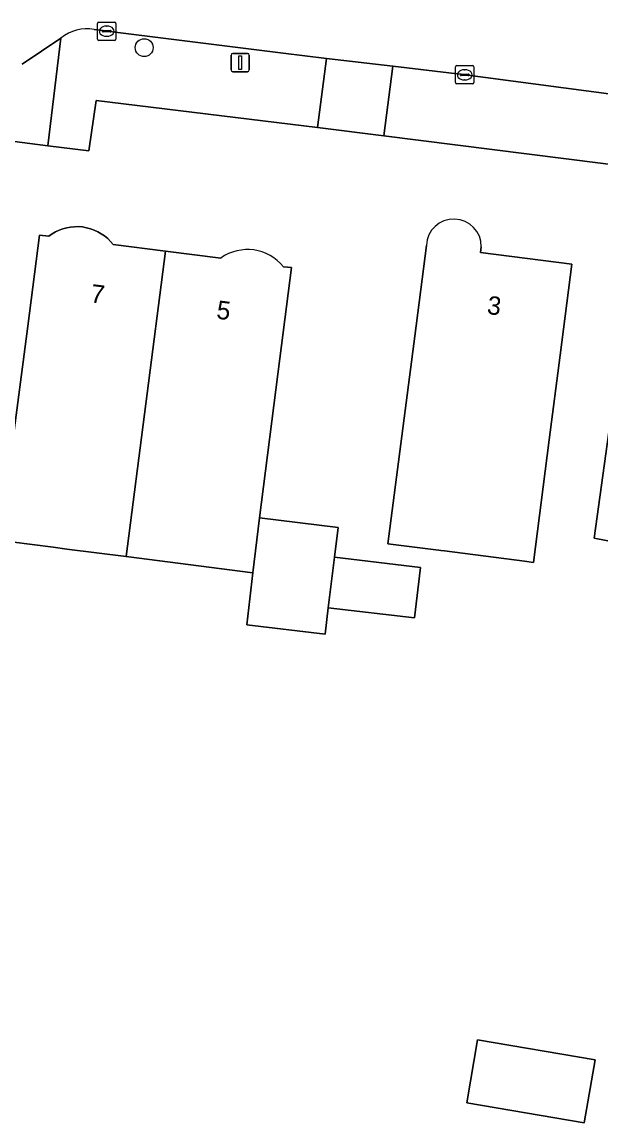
# Model space of a CAD drawing. Extents: x 161258 to 161838, y 380833 to 381727.
# Drawn here: x 161705.9 to 161737.5, y 381275.5 to 381335.5 of the extents above; entities that cross this region are included whole.
import ezdxf

# ---------------------------------------------------------------- set-up
doc = ezdxf.new("R2010")
doc.units = 0
for name, color, linetype in [('IMGEO_Boom', 7, 'Continuous'), ('IMGEO_Erf', 7, 'Continuous'), ('IMGEO_Kolk', 7, 'Continuous'), ('IMGEO_Lichtmast', 7, 'Continuous'), ('IMGEO_Pand', 7, 'Continuous'), ('IMGEO_Pand_nummerreeks', 7, 'Continuous'), ('IMGEO_Rijbaan_lokaal_open', 7, 'Continuous'), ('IMGEO_Voetpad_open', 7, 'Continuous')]:
    doc.layers.add(name, color=color, linetype=linetype)

msp = doc.modelspace()

# ---------------------------------------------------------------- linework, layer by layer
at = {"layer": 'IMGEO_Boom'}
msp.add_circle((161712.597, 381334.125), 0.489, dxfattribs=at)
at = {"layer": 'IMGEO_Erf'}
for points in [[(161769.385, 381323.827), (161746.772, 381326.654), (161743.36, 381327.08), (161725.655, 381329.321), (161722.039, 381329.767), (161709.981, 381331.253), (161709.582, 381328.497), (161707.353, 381328.782), (161703.558, 381329.267), (161690.653, 381330.917), (161687.235, 381331.354), (161668.929, 381333.694), (161666.159, 381311.809), (161665.334, 381305.29), (161663, 381286.849), (161662.641, 381284.007), (161661.905, 381278.195)], [(161705.374, 381312.146), (161706.257, 381318.95), (161706.894, 381323.909), (161707.4, 381323.844), (161707.578, 381323.97), (161707.766, 381324.08), (161707.963, 381324.173), (161708.168, 381324.249), (161708.378, 381324.307), (161708.592, 381324.346), (161708.809, 381324.366), (161709.028, 381324.367), (161709.245, 381324.349), (161709.46, 381324.312), (161709.671, 381324.257), (161709.876, 381324.183), (161710.074, 381324.092), (161710.263, 381323.984), (161710.442, 381323.86), (161710.61, 381323.721), (161710.765, 381323.567), (161710.906, 381323.401), (161713.762, 381323.036), (161716.766, 381322.653)], [(161728.64, 381306.727), (161728.481, 381306.747), (161725.877, 381307.082), (161727.331, 381318.39), (161727.969, 381323.349)], [(161730.961, 381323.268), (161730.922, 381322.961), (161735.884, 381322.323), (161735.247, 381317.364), (161734.653, 381312.742), (161733.795, 381306.063), (161733.306, 381306.126), (161728.947, 381306.687), (161728.754, 381306.712), (161728.64, 381306.727)], [(161720.192, 381322.181), (161720.623, 381322.136), (161719.986, 381317.177), (161718.87, 381308.489), (161723.163, 381307.975), (161722.963, 381306.35), (161727.651, 381305.788), (161727.312, 381303.035), (161722.623, 381303.596), (161722.446, 381302.157), (161718.19, 381302.666), (161718.52, 381305.488)], [(161718.52, 381305.488), (161711.608, 381306.379), (161708.38, 381306.795), (161707.639, 381306.89), (161705.347, 381307.185)]]:
    msp.add_lwpolyline(points, dxfattribs=at)
for points in [[(161746.736, 381295.425), (161742.281, 381296.299), (161743.072, 381300.327), (161744.676, 381300.012), (161745.156, 381302.458), (161738.434, 381303.783), (161739.069, 381307.013), (161737.099, 381307.382), (161738.382, 381316.587), (161741.592, 381315.986), (161740.78, 381310.162), (161746.989, 381309), (161746.362, 381305.647), (161745.82, 381302.749), (161747.205, 381302.476), (161755.905, 381300.762), (161760.811, 381299.8), (161760.341, 381297.293), (161761.078, 381297.154), (161760.433, 381293.711), (161759.696, 381293.85), (161759.522, 381292.917), (161754.616, 381293.879)], [(161730.169, 381276.596), (161730.757, 381280.046), (161737.157, 381278.957), (161736.569, 381275.506)]]:
    msp.add_lwpolyline(points, close=True, dxfattribs=at)
for centre, radius, start, end in [((161729.464, 381323.286), 1.497, 359.31739, 177.58112), ((161718.228, 381320.592), 2.527, 38.97192, 125.33956)]:
    msp.add_arc(centre, radius, start, end, dxfattribs=at)
at = {"layer": 'IMGEO_Kolk'}
for p, q in [((161710.057, 381334.596), (161710.057, 381335.448)), ((161710.132, 381335.522), (161710.984, 381335.522)), ((161710.545, 381335.302), (161710.57, 381335.302)), ((161711.058, 381335.448), (161711.058, 381334.596)), ((161710.316, 381335.016), (161710.316, 381335.028)), ((161710.754, 381334.979), (161710.356, 381334.979)), ((161710.359, 381335.065), (161710.757, 381335.065)), ((161710.568, 381334.742), (161710.543, 381334.742)), ((161710.8, 381335.028), (161710.8, 381335.016)), ((161710.984, 381334.522), (161710.132, 381334.522)), ((161729.557, 381332.219), (161729.557, 381333.071)), ((161729.632, 381333.145), (161730.484, 381333.145)), ((161730.045, 381332.925), (161730.07, 381332.925)), ((161730.558, 381333.071), (161730.558, 381332.219)), ((161729.816, 381332.639), (161729.816, 381332.651)), ((161730.254, 381332.602), (161729.856, 381332.602)), ((161729.859, 381332.688), (161730.257, 381332.688)), ((161730.068, 381332.365), (161730.043, 381332.365)), ((161730.3, 381332.651), (161730.3, 381332.639)), ((161730.484, 381332.145), (161729.632, 381332.145))]:
    msp.add_line(p, q, dxfattribs=at)
for points in [[(161710.057, 381334.596), (161710.057, 381335.448)], [(161710.132, 381335.522), (161710.984, 381335.522)], [(161711.058, 381335.448), (161711.058, 381334.596)], [(161710.984, 381334.522), (161710.132, 381334.522)], [(161729.557, 381332.219), (161729.557, 381333.071)], [(161729.632, 381333.145), (161730.484, 381333.145)], [(161730.558, 381333.071), (161730.558, 381332.219)], [(161730.484, 381332.145), (161729.632, 381332.145)]]:
    msp.add_lwpolyline(points, dxfattribs=at)
for centre, radius, start, end in [((161710.134, 381335.446), 0.0765, 91.55205, 178.44795), ((161710.134, 381335.446), 0.0765, 91.55205, 178.44795), ((161710.982, 381335.446), 0.0765, 1.55205, 88.44795), ((161710.982, 381335.446), 0.0765, 1.55205, 88.44795), ((161710.134, 381334.598), 0.0765, 181.55205, 268.44795), ((161710.134, 381334.598), 0.0765, 181.55205, 268.44795), ((161710.356, 381335.025), 0.0403, 85.87752, 175.75265), ((161710.353, 381335.015), 0.0366, 178.93798, 274.71019), ((161710.757, 381335.022), 0.043, 264.86636, 352.45326), ((161710.761, 381335.027), 0.0386, 1.73085, 96.63898), ((161710.982, 381334.598), 0.0765, 271.55205, 358.44795), ((161710.982, 381334.598), 0.0765, 271.55205, 358.44795), ((161729.634, 381333.069), 0.0765, 91.55205, 178.44795), ((161729.634, 381333.069), 0.0765, 91.55205, 178.44795), ((161730.482, 381333.069), 0.0765, 1.55205, 88.44795), ((161730.482, 381333.069), 0.0765, 1.55205, 88.44795), ((161729.634, 381332.221), 0.0765, 181.55205, 268.44795), ((161729.634, 381332.221), 0.0765, 181.55205, 268.44795), ((161729.856, 381332.648), 0.0403, 85.87752, 175.75265), ((161729.853, 381332.638), 0.0366, 178.93798, 274.71019), ((161730.257, 381332.645), 0.043, 264.86636, 352.45326), ((161730.261, 381332.65), 0.0386, 1.73085, 96.63898), ((161730.482, 381332.221), 0.0765, 271.55205, 358.44795), ((161730.482, 381332.221), 0.0765, 271.55205, 358.44795)]:
    msp.add_arc(centre, radius, start, end, dxfattribs=at)
for centre, major_axis, ratio, start_param, end_param in [((161710.544, 381335.022), (-0.387, 0.002), 0.722429, 4.712389, 7.853982), ((161710.569, 381335.022), (-0.39, 0.002), 0.717154, 1.570796, 4.712389), ((161730.044, 381332.645), (-0.387, 0.002), 0.722429, 4.712389, 7.853982), ((161730.069, 381332.645), (-0.39, 0.002), 0.717154, 1.570796, 4.712389)]:
    msp.add_ellipse(centre, major_axis=major_axis, ratio=ratio, start_param=start_param, end_param=end_param, dxfattribs=at)
at = {"layer": 'IMGEO_Lichtmast'}
for p, q in [((161717.331, 381332.91), (161717.331, 381333.71)), ((161717.331, 381333.71), (161717.331, 381332.91)), ((161717.431, 381333.81), (161718.221, 381333.81)), ((161718.221, 381333.81), (161717.431, 381333.81)), ((161718.321, 381333.71), (161718.321, 381332.91)), ((161718.321, 381332.91), (161718.321, 381333.71)), ((161718.221, 381332.81), (161717.431, 381332.81)), ((161717.431, 381332.81), (161718.221, 381332.81))]:
    msp.add_line(p, q, dxfattribs=at)
msp.add_lwpolyline([(161717.751, 381333.685), (161717.901, 381333.685), (161717.901, 381332.935), (161717.751, 381332.935), (161717.751, 381333.685)], dxfattribs=at)
for centre, start, end in [((161717.431, 381333.71), 90, 180), ((161717.431, 381333.71), 90, 180), ((161718.221, 381333.71), 0, 90), ((161718.221, 381333.71), 360, 90), ((161717.431, 381332.91), 180, 270), ((161717.431, 381332.91), 180, 270), ((161718.221, 381332.91), 270, 0), ((161718.221, 381332.91), 270, 0)]:
    msp.add_arc(centre, 0.1, start, end, dxfattribs=at)
at = {"layer": 'IMGEO_Pand'}
for points in [[(161705.347, 381307.185), (161707.639, 381306.89), (161708.38, 381306.795), (161711.608, 381306.379), (161713.762, 381323.036), (161710.906, 381323.401), (161710.765, 381323.567), (161710.61, 381323.721), (161710.442, 381323.86), (161710.263, 381323.984), (161710.074, 381324.092), (161709.876, 381324.183), (161709.671, 381324.257), (161709.46, 381324.312), (161709.245, 381324.349), (161709.028, 381324.367), (161708.809, 381324.366), (161708.592, 381324.346), (161708.378, 381324.307), (161708.168, 381324.249), (161707.963, 381324.173), (161707.766, 381324.08), (161707.578, 381323.97), (161707.4, 381323.844), (161706.894, 381323.909), (161706.257, 381318.95), (161705.374, 381312.146)], [(161727.969, 381323.349), (161727.331, 381318.39), (161725.877, 381307.082), (161728.481, 381306.747), (161728.64, 381306.727), (161728.754, 381306.712), (161728.947, 381306.687), (161733.306, 381306.126), (161733.795, 381306.063), (161734.653, 381312.742), (161735.247, 381317.364)], [(161735.247, 381317.364), (161735.884, 381322.323), (161730.922, 381322.961), (161730.961, 381323.268)], [(161716.766, 381322.653), (161713.762, 381323.036), (161711.608, 381306.379), (161718.52, 381305.488), (161718.87, 381308.489), (161719.986, 381317.177)], [(161719.986, 381317.177), (161720.623, 381322.136), (161720.192, 381322.181)]]:
    msp.add_lwpolyline(points, dxfattribs=at)
for points in [[(161739.069, 381307.013), (161741.466, 381306.564), (161746.362, 381305.647), (161746.989, 381309), (161740.78, 381310.162), (161741.592, 381315.986), (161738.382, 381316.587), (161737.099, 381307.382)], [(161722.963, 381306.35), (161723.163, 381307.975), (161718.87, 381308.489), (161718.52, 381305.488), (161718.19, 381302.666), (161722.446, 381302.157), (161722.623, 381303.596)], [(161722.963, 381306.35), (161722.623, 381303.596), (161727.312, 381303.035), (161727.651, 381305.788)], [(161736.569, 381275.506), (161737.157, 381278.957), (161730.757, 381280.046), (161730.169, 381276.596)]]:
    msp.add_lwpolyline(points, close=True, dxfattribs=at)
for centre, radius, start, end in [((161729.464, 381323.286), 1.497, 359.31739, 177.58112), ((161718.228, 381320.592), 2.527, 38.97192, 125.33956)]:
    msp.add_arc(centre, radius, start, end, dxfattribs=at)
at = {"layer": 'IMGEO_Rijbaan_lokaal_open'}
for points in [[(161705.944, 381333.229), (161708.066, 381334.645)], [(161709.868, 381335.11), (161710.44, 381335.039), (161720.164, 381333.823), (161722.528, 381333.542), (161726.14, 381333.113), (161729.96, 381332.659), (161739.408, 381331.414), (161743.86, 381330.828), (161747.288, 381330.383), (161751.089, 381329.889), (161760.466, 381328.497), (161768.822, 381327.424)]]:
    msp.add_lwpolyline(points, dxfattribs=at)
msp.add_arc((161709.455, 381332.986), 2.164, 79.00049, 129.93818, dxfattribs=at)
at = {"layer": 'IMGEO_Voetpad_open'}
for points in [[(161701.883, 381332.375), (161700.036, 381332.619), (161699.94, 381331.581), (161703.553, 381331.378), (161703.819, 381331.392), (161703.558, 381329.267), (161707.353, 381328.782), (161708.066, 381334.645)], [(161708.066, 381334.645), (161705.944, 381333.229)], [(161708.066, 381334.645), (161707.353, 381328.782), (161709.582, 381328.497), (161709.981, 381331.253), (161722.039, 381329.767), (161722.528, 381333.542)], [(161722.528, 381333.542), (161720.164, 381333.823), (161710.44, 381335.039), (161709.868, 381335.11)]]:
    msp.add_lwpolyline(points, dxfattribs=at)
for points in [[(161726.14, 381333.113), (161722.528, 381333.542), (161722.039, 381329.767), (161725.655, 381329.321)], [(161739.408, 381331.414), (161729.96, 381332.659), (161726.14, 381333.113), (161725.655, 381329.321), (161743.36, 381327.08), (161743.7, 381329.615), (161739.222, 381330.253)]]:
    msp.add_lwpolyline(points, close=True, dxfattribs=at)
msp.add_arc((161709.455, 381332.986), 2.164, 79.00049, 129.93818, dxfattribs=at)

# ---------------------------------------------------------------- texts
at = {"layer": 'IMGEO_Pand_nummerreeks'}
for s, rotation, p in [('7', 352.64322, (161709.632, 381320.248)), ('5', 352.64322, (161716.496, 381319.361)), ('3', 352.67187, (161731.235, 381319.615))]:
    msp.add_text(s, height=1, rotation=rotation, dxfattribs=at).set_placement(p)

doc.saveas('drawing.dxf')
